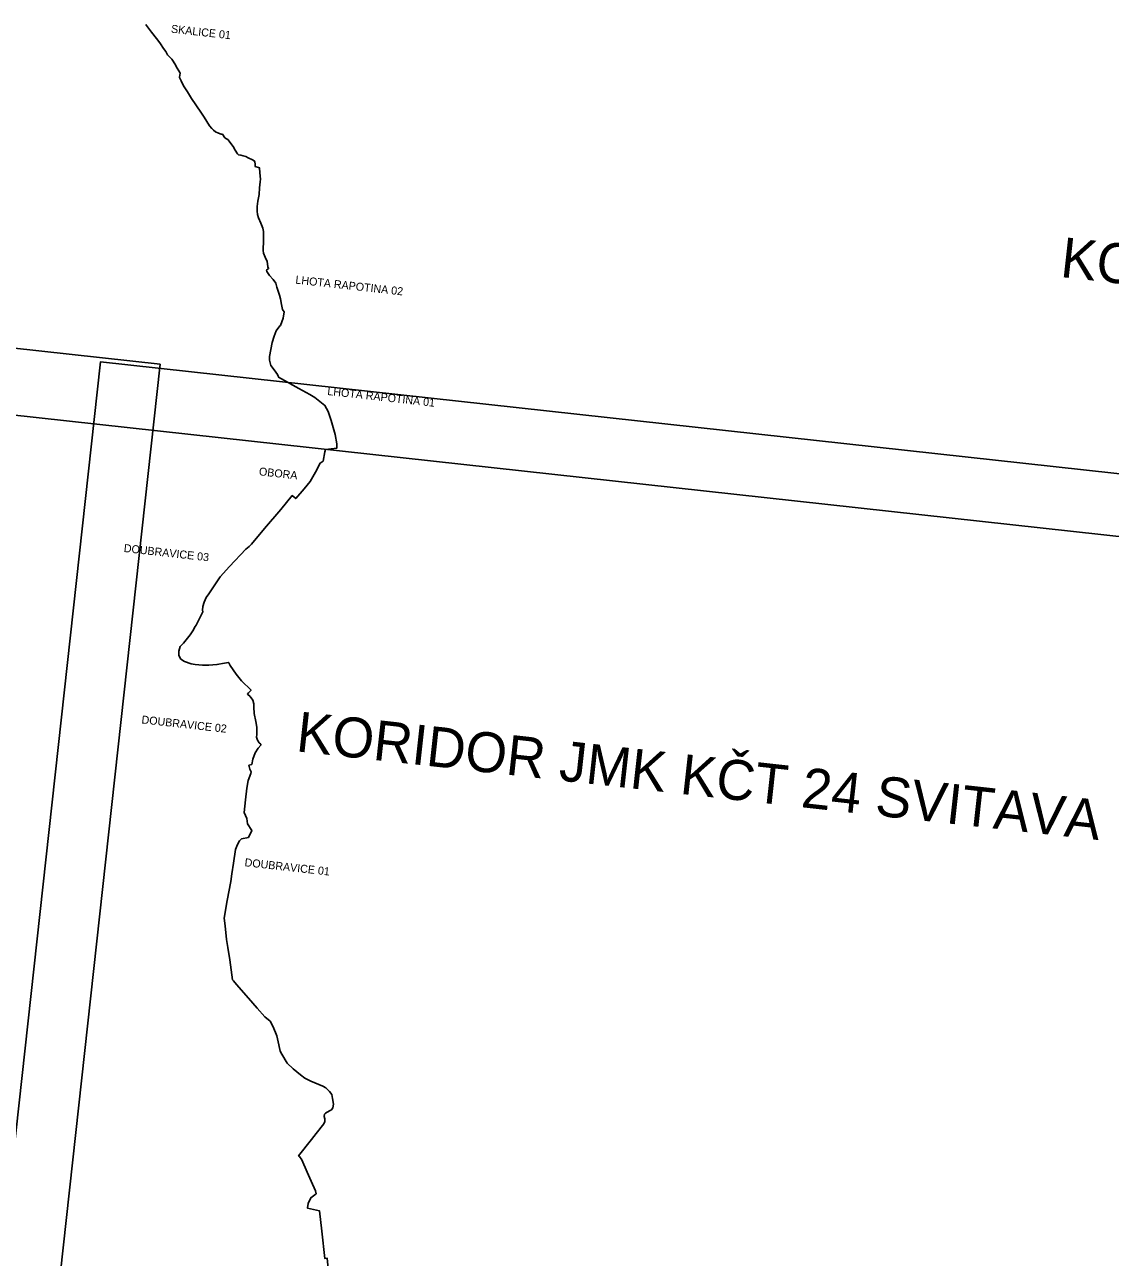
# Model space of a CAD drawing. Extents: x -678204 to -526855, y -1228851 to -1110393.
# Drawn here: x -595642 to -587497, y -1138238 to -1128993 of the extents above; entities that cross this region are included whole.
import ezdxf

# ---------------------------------------------------------------- set-up
doc = ezdxf.new("R2010")
doc.units = 0
for name, color, linetype in [('00_n_cyklo popisy', 7, 'Continuous'), ('00_n_cyklo popisy detaily', 7, 'Continuous'), ('00_n_cyklo provereni rekreacni hlavni', 7, 'Continuous'), ('00_n_cyklo prujezdne podminecne rekreacni hlavni', 7, 'Continuous'), ('00_n_cyklo prujezdne rekreacni hlavni', 7, 'Continuous'), ('00_n_cyklo trasovani rekreacni hlavni', 7, 'Continuous'), ('_HELP BIG', 7, 'Continuous')]:
    doc.layers.add(name, color=color, linetype=linetype)

msp = doc.modelspace()

# ---------------------------------------------------------------- linework, layer by layer
at = {"layer": '00_n_cyklo provereni rekreacni hlavni'}
for points in [[(-594307.6, -1133401.8), (-594305.3, -1133397.5), (-594307.6, -1133385.3), (-594304.7, -1133356.3), (-594295.4, -1133324.1), (-594279.3, -1133289), (-594259.6, -1133260.6), (-594194.6, -1133164.6), (-594174.6, -1133134), (-594103.7, -1133057), (-593983, -1132926.2), (-593957.9, -1132905.6), (-593939.2, -1132890.1), (-593843.5, -1132772.6), (-593719.1, -1132629.3), (-593633.8, -1132524.8), (-593607.4, -1132547.3), (-593545.4, -1132473.4), (-593498.6, -1132419.8), (-593458.6, -1132349.9), (-593425.9, -1132280.6), (-593401.2, -1132265.6), (-593390.6, -1132197.9), (-593385.1, -1132179.2), (-593363.2, -1132176.3), (-593298.7, -1132168.2), (-593300.6, -1132136.3), (-593311.5, -1132066.1), (-593342.1, -1131962.3), (-593364.7, -1131893.4), (-593388.5, -1131848.6), (-593464.8, -1131790), (-593503.5, -1131767.4), (-593584.3, -1131721.7), (-593736.2, -1131637.8), (-593737.3, -1131633.9)], [(-593870, -1134395.7), (-593869.3, -1134389.8), (-593881.3, -1134378.2), (-593894.9, -1134358.6), (-593902.6, -1134337.6), (-593900, -1134316.4), (-593900.3, -1134260.6), (-593908.4, -1134218.1), (-593918.7, -1134159.5), (-593921.6, -1134110.9), (-593921.6, -1134086.7), (-593930.1, -1134057.9), (-593950.4, -1134030.9), (-593970.1, -1134013.4), (-593961.3, -1134003.5)]]:
    msp.add_lwpolyline(points, dxfattribs=at)
at = {"layer": '00_n_cyklo prujezdne podminecne rekreacni hlavni'}
for points in [[(-594476.9, -1129352.3), (-594504.7, -1129307.5), (-594509.2, -1129294.9), (-594537.2, -1129252.4), (-594571, -1129219.9), (-594582.9, -1129195.1), (-594600.3, -1129171.2), (-594622.5, -1129137.1), (-594641.5, -1129109.1), (-594653.1, -1129097.8), (-594690.8, -1129050.1), (-594728.1, -1128999.2), (-594732.4, -1128991.8)], [(-594127.2, -1129848.2), (-594139.8, -1129841), (-594157.8, -1129815.5), (-594167.8, -1129813.9), (-594186.8, -1129806.5), (-594208.7, -1129795.9), (-594225.1, -1129783.3), (-594238.6, -1129770.8), (-594253.8, -1129750.8), (-594295.6, -1129686.4), (-594320.1, -1129650.3), (-594389, -1129546.5), (-594420.3, -1129495.6), (-594448.9, -1129452.1), (-594466.3, -1129415.1), (-594479.2, -1129390.3), (-594480.5, -1129386.1), (-594474.1, -1129356.8), (-594476.9, -1129352.3)], [(-593737.3, -1131633.9), (-593738.8, -1131629.1), (-593745.9, -1131617.2), (-593770.3, -1131581.4), (-593794.2, -1131548.2), (-593805.5, -1131508), (-593804.3, -1131480.9), (-593785.7, -1131377.8), (-593770, -1131328.7), (-593755.9, -1131289.2), (-593728.3, -1131252), (-593723.4, -1131248.2), (-593703.1, -1131194), (-593693.8, -1131146), (-593701.2, -1131137.3), (-593708.3, -1131129), (-593713.8, -1131091), (-593721.5, -1131049.1), (-593730.8, -1131021), (-593749.2, -1130961.1), (-593757.6, -1130932.1), (-593777.8, -1130903.5), (-593805.2, -1130873.8), (-593823.6, -1130845.5), (-593827.1, -1130833.6), (-593814.2, -1130824.9), (-593812, -1130822.6), (-593817.1, -1130808.4), (-593821, -1130785.9), (-593821.3, -1130770.1), (-593837.4, -1130736.3), (-593850.3, -1130707.3), (-593852.2, -1130685.7), (-593850.6, -1130609.7), (-593849.3, -1130570.7), (-593850, -1130543.6), (-593854.8, -1130518.2), (-593870, -1130481.8), (-593887, -1130441.5), (-593895.4, -1130416.3), (-593898.6, -1130391.4), (-593896.2, -1130356.4), (-593891.2, -1130316.3), (-593883.1, -1130266.4), (-593881.1, -1130218), (-593874.1, -1130171.4), (-593873.4, -1130151.7), (-593876.3, -1130103.3), (-593880.2, -1130065.6), (-593912.6, -1130056.6), (-593912.2, -1130039.4), (-593913.8, -1130022.7), (-593919, -1130013.3), (-593932.2, -1130007), (-593964.3, -1129991), (-593983.6, -1129982.9), (-594001.8, -1129976.8), (-594020.9, -1129973), (-594036.6, -1129970), (-594046, -1129962.5), (-594062.3, -1129933.2), (-594076.9, -1129907.8), (-594116.3, -1129854.5), (-594127.2, -1129848.2)], [(-593519.3, -1137866.7), (-593515.2, -1137833), (-593495.4, -1137790.8), (-593455.4, -1137760.3), (-593460, -1137738.7), (-593493.2, -1137666.6), (-593521.5, -1137598.3), (-593562.1, -1137507.1), (-593580.8, -1137481.6), (-593586.6, -1137477.5), (-593490.1, -1137353.6), (-593454.6, -1137309.6), (-593397.9, -1137235.3), (-593389.9, -1137219.5), (-593390.5, -1137200.2), (-593395.4, -1137181.8), (-593392.2, -1137165.1), (-593385.4, -1137156.4), (-593355.4, -1137139.6), (-593340.3, -1137131.2), (-593330.3, -1137116.7), (-593325.5, -1137089.3), (-593331.9, -1137047.5), (-593338.4, -1137015.9), (-593355.8, -1136994.6), (-593381.8, -1136966.9), (-593405.4, -1136954), (-593494.9, -1136917.6), (-593538.7, -1136894.4), (-593573.1, -1136868.3), (-593626.6, -1136824.9), (-593671.7, -1136782), (-593712.6, -1136713.4), (-593724.8, -1136690.8), (-593733.8, -1136643.5), (-593748.7, -1136576.5), (-593778.3, -1136508.2), (-593800.2, -1136467.3), (-593840.8, -1136433.1), (-593896.5, -1136368.7), (-593961.5, -1136294), (-594052, -1136191.2), (-594075.2, -1136163.8), (-594083.5, -1136156.2), (-594103.5, -1136006.1), (-594117, -1135914.3), (-594126.3, -1135853.7), (-594138.6, -1135751.2), (-594146, -1135693.9), (-594123.1, -1135562.8), (-594096.1, -1135419.4), (-594087.7, -1135362.4), (-594073.8, -1135281.9), (-594059, -1135180.1), (-594045.5, -1135141.7), (-594030.4, -1135113.4), (-594015.2, -1135099.9), (-593963.1, -1135087.9), (-593937.9, -1135036.4), (-593969.2, -1134987.7), (-593973.7, -1134946.8), (-593993.7, -1134902.1), (-593985.6, -1134806.4), (-593975.3, -1134720), (-593965.6, -1134661.7), (-593943.7, -1134609.9), (-593941.8, -1134597.6), (-593951.5, -1134575.4), (-593959.5, -1134547), (-593938.6, -1134540.9), (-593929.9, -1134501.9), (-593911.9, -1134453.6), (-593890.6, -1134418.2), (-593870, -1134395.9), (-593870, -1134395.7)]]:
    msp.add_lwpolyline(points, dxfattribs=at)
at = {"layer": '00_n_cyklo prujezdne rekreacni hlavni'}
for points in [[(-593961.3, -1134003.5), (-593956, -1133997.6), (-593943.1, -1133984.6), (-594014.6, -1133914.7), (-594054.2, -1133865.1), (-594077.4, -1133831), (-594099.6, -1133800.1), (-594110.9, -1133779.8), (-594112.8, -1133775.9), (-594143.1, -1133782.3), (-594198.8, -1133792.3), (-594260, -1133795.9), (-594307.7, -1133795.9), (-594363.1, -1133790.7), (-594392.4, -1133785.6), (-594443.6, -1133768.5), (-594470, -1133751.4), (-594484.5, -1133724.7), (-594485.4, -1133690.5), (-594475.8, -1133655.7), (-594450.3, -1133630.6), (-594399.1, -1133569.7), (-594380.5, -1133539.8), (-594363.1, -1133507.6), (-594356, -1133496), (-594307.6, -1133401.8)], [(-593481.4, -1138895.2), (-593508, -1138824.8), (-593325.4, -1138733), (-593318.5, -1138728.9), (-593356.2, -1138398.5), (-593372.6, -1138242.9), (-593390.1, -1138245.7), (-593412, -1138042.2), (-593428.9, -1137889.4), (-593519.7, -1137870.2), (-593519.3, -1137866.7)]]:
    msp.add_lwpolyline(points, dxfattribs=at)
at = {"layer": '00_n_cyklo trasovani rekreacni hlavni'}
for points in [[(-594476.9, -1129352.3), (-594504.7, -1129307.5), (-594509.2, -1129294.9), (-594537.2, -1129252.4), (-594571, -1129219.9), (-594582.9, -1129195.1), (-594600.3, -1129171.2), (-594622.5, -1129137.1), (-594641.5, -1129109.1), (-594653.1, -1129097.8), (-594690.8, -1129050.1), (-594728.1, -1128999.2), (-594732.4, -1128991.8)], [(-594127.2, -1129848.2), (-594139.8, -1129841), (-594157.8, -1129815.5), (-594167.8, -1129813.9), (-594186.8, -1129806.5), (-594208.7, -1129795.9), (-594225.1, -1129783.3), (-594238.6, -1129770.8), (-594253.8, -1129750.8), (-594295.6, -1129686.4), (-594320.1, -1129650.3), (-594389, -1129546.5), (-594420.3, -1129495.6), (-594448.9, -1129452.1), (-594466.3, -1129415.1), (-594479.2, -1129390.3), (-594480.5, -1129386.1), (-594474.1, -1129356.8), (-594476.9, -1129352.3)], [(-593737.3, -1131633.9), (-593738.8, -1131629.1), (-593745.9, -1131617.2), (-593770.3, -1131581.4), (-593794.2, -1131548.2), (-593805.5, -1131508), (-593804.3, -1131480.9), (-593785.7, -1131377.8), (-593770, -1131328.7), (-593755.9, -1131289.2), (-593728.3, -1131252), (-593723.4, -1131248.2), (-593703.1, -1131194), (-593693.8, -1131146), (-593701.2, -1131137.3), (-593708.3, -1131129), (-593713.8, -1131091), (-593721.5, -1131049.1), (-593730.8, -1131021), (-593749.2, -1130961.1), (-593757.6, -1130932.1), (-593777.8, -1130903.5), (-593805.2, -1130873.8), (-593823.6, -1130845.5), (-593827.1, -1130833.6), (-593814.2, -1130824.9), (-593812, -1130822.6), (-593817.1, -1130808.4), (-593821, -1130785.9), (-593821.3, -1130770.1), (-593837.4, -1130736.3), (-593850.3, -1130707.3), (-593852.2, -1130685.7), (-593850.6, -1130609.7), (-593849.3, -1130570.7), (-593850, -1130543.6), (-593854.8, -1130518.2), (-593870, -1130481.8), (-593887, -1130441.5), (-593895.4, -1130416.3), (-593898.6, -1130391.4), (-593896.2, -1130356.4), (-593891.2, -1130316.3), (-593883.1, -1130266.4), (-593881.1, -1130218), (-593874.1, -1130171.4), (-593873.4, -1130151.7), (-593876.3, -1130103.3), (-593880.2, -1130065.6), (-593912.6, -1130056.6), (-593912.2, -1130039.4), (-593913.8, -1130022.7), (-593919, -1130013.3), (-593932.2, -1130007), (-593964.3, -1129991), (-593983.6, -1129982.9), (-594001.8, -1129976.8), (-594020.9, -1129973), (-594036.6, -1129970), (-594046, -1129962.5), (-594062.3, -1129933.2), (-594076.9, -1129907.8), (-594116.3, -1129854.5), (-594127.2, -1129848.2)], [(-594307.6, -1133401.8), (-594305.3, -1133397.5), (-594307.6, -1133385.3), (-594304.7, -1133356.3), (-594295.4, -1133324.1), (-594279.3, -1133289), (-594259.6, -1133260.6), (-594194.6, -1133164.6), (-594174.6, -1133134), (-594103.7, -1133057), (-593983, -1132926.2), (-593957.9, -1132905.6), (-593939.2, -1132890.1), (-593843.5, -1132772.6), (-593719.1, -1132629.3), (-593633.8, -1132524.8), (-593607.4, -1132547.3), (-593545.4, -1132473.4), (-593498.6, -1132419.8), (-593458.6, -1132349.9), (-593425.9, -1132280.6), (-593401.2, -1132265.6), (-593390.6, -1132197.9), (-593385.1, -1132179.2), (-593363.2, -1132176.3), (-593298.7, -1132168.2), (-593300.6, -1132136.3), (-593311.5, -1132066.1), (-593342.1, -1131962.3), (-593364.7, -1131893.4), (-593388.5, -1131848.6), (-593464.8, -1131790), (-593503.5, -1131767.4), (-593584.3, -1131721.7), (-593736.2, -1131637.8), (-593737.3, -1131633.9)], [(-593961.3, -1134003.5), (-593956, -1133997.6), (-593943.1, -1133984.6), (-594014.6, -1133914.7), (-594054.2, -1133865.1), (-594077.4, -1133831), (-594099.6, -1133800.1), (-594110.9, -1133779.8), (-594112.8, -1133775.9), (-594143.1, -1133782.3), (-594198.8, -1133792.3), (-594260, -1133795.9), (-594307.7, -1133795.9), (-594363.1, -1133790.7), (-594392.4, -1133785.6), (-594443.6, -1133768.5), (-594470, -1133751.4), (-594484.5, -1133724.7), (-594485.4, -1133690.5), (-594475.8, -1133655.7), (-594450.3, -1133630.6), (-594399.1, -1133569.7), (-594380.5, -1133539.8), (-594363.1, -1133507.6), (-594356, -1133496), (-594307.6, -1133401.8)], [(-593870, -1134395.7), (-593869.3, -1134389.8), (-593881.3, -1134378.2), (-593894.9, -1134358.6), (-593902.6, -1134337.6), (-593900, -1134316.4), (-593900.3, -1134260.6), (-593908.4, -1134218.1), (-593918.7, -1134159.5), (-593921.6, -1134110.9), (-593921.6, -1134086.7), (-593930.1, -1134057.9), (-593950.4, -1134030.9), (-593970.1, -1134013.4), (-593961.3, -1134003.5)], [(-593519.3, -1137866.7), (-593515.2, -1137833), (-593495.4, -1137790.8), (-593455.4, -1137760.3), (-593460, -1137738.7), (-593493.2, -1137666.6), (-593521.5, -1137598.3), (-593562.1, -1137507.1), (-593580.8, -1137481.6), (-593586.6, -1137477.5), (-593490.1, -1137353.6), (-593454.6, -1137309.6), (-593397.9, -1137235.3), (-593389.9, -1137219.5), (-593390.5, -1137200.2), (-593395.4, -1137181.8), (-593392.2, -1137165.1), (-593385.4, -1137156.4), (-593355.4, -1137139.6), (-593340.3, -1137131.2), (-593330.3, -1137116.7), (-593325.5, -1137089.3), (-593331.9, -1137047.5), (-593338.4, -1137015.9), (-593355.8, -1136994.6), (-593381.8, -1136966.9), (-593405.4, -1136954), (-593494.9, -1136917.6), (-593538.7, -1136894.4), (-593573.1, -1136868.3), (-593626.6, -1136824.9), (-593671.7, -1136782), (-593712.6, -1136713.4), (-593724.8, -1136690.8), (-593733.8, -1136643.5), (-593748.7, -1136576.5), (-593778.3, -1136508.2), (-593800.2, -1136467.3), (-593840.8, -1136433.1), (-593896.5, -1136368.7), (-593961.5, -1136294), (-594052, -1136191.2), (-594075.2, -1136163.8), (-594083.5, -1136156.2), (-594103.5, -1136006.1), (-594117, -1135914.3), (-594126.3, -1135853.7), (-594138.6, -1135751.2), (-594146, -1135693.9), (-594123.1, -1135562.8), (-594096.1, -1135419.4), (-594087.7, -1135362.4), (-594073.8, -1135281.9), (-594059, -1135180.1), (-594045.5, -1135141.7), (-594030.4, -1135113.4), (-594015.2, -1135099.9), (-593963.1, -1135087.9), (-593937.9, -1135036.4), (-593969.2, -1134987.7), (-593973.7, -1134946.8), (-593993.7, -1134902.1), (-593985.6, -1134806.4), (-593975.3, -1134720), (-593965.6, -1134661.7), (-593943.7, -1134609.9), (-593941.8, -1134597.6), (-593951.5, -1134575.4), (-593959.5, -1134547), (-593938.6, -1134540.9), (-593929.9, -1134501.9), (-593911.9, -1134453.6), (-593890.6, -1134418.2), (-593870, -1134395.9), (-593870, -1134395.7)], [(-593481.4, -1138895.2), (-593508, -1138824.8), (-593325.4, -1138733), (-593318.5, -1138728.9), (-593356.2, -1138398.5), (-593372.6, -1138242.9), (-593390.1, -1138245.7), (-593412, -1138042.2), (-593428.9, -1137889.4), (-593519.7, -1137870.2), (-593519.3, -1137866.7)]]:
    msp.add_lwpolyline(points, dxfattribs=at)
at = {"layer": '_HELP BIG'}
for points in [[(-580036.8, -1133644.2), (-608324.2, -1130538), (-606112.1, -1110393), (-577824.7, -1113499.2)], [(-617877.4, -1157614.7), (-614771.3, -1129327.4), (-594626.3, -1131539.4), (-597732.4, -1159826.8)], [(-598180, -1159809.1), (-595073.9, -1131521.8), (-574928.9, -1133733.9), (-578035.1, -1162021.2)]]:
    msp.add_lwpolyline(points, close=True, dxfattribs=at)

# ---------------------------------------------------------------- texts
at = {"layer": '00_n_cyklo popisy'}
for s, p in [('KORIDOR JMK KCT 5', (-587878.9, -1130884.5)), ('KORIDOR JMK KČT 24 SVITAVA', (-593612, -1134441.7))]:
    msp.add_text(s, height=300, rotation=353.68355, dxfattribs=at).set_placement(p)
at = {"layer": '00_n_cyklo popisy detaily'}
for s, p in [('SKALICE 01', (-594546, -1129052.8)), ('LHOTA RAPOTINA 02', (-593612.5, -1130934.8)), ('LHOTA RAPOTINA 01', (-593373.2, -1131770)), ('OBORA', (-593886.4, -1132372.2)), ('DOUBRAVICE 03', (-594900.3, -1132947.4)), ('DOUBRAVICE 02', (-594767.3, -1134233.1)), ('DOUBRAVICE 01', (-593994, -1135304.1))]:
    msp.add_text(s, height=60, rotation=353.68355, dxfattribs=at).set_placement(p)

doc.saveas('drawing.dxf')
